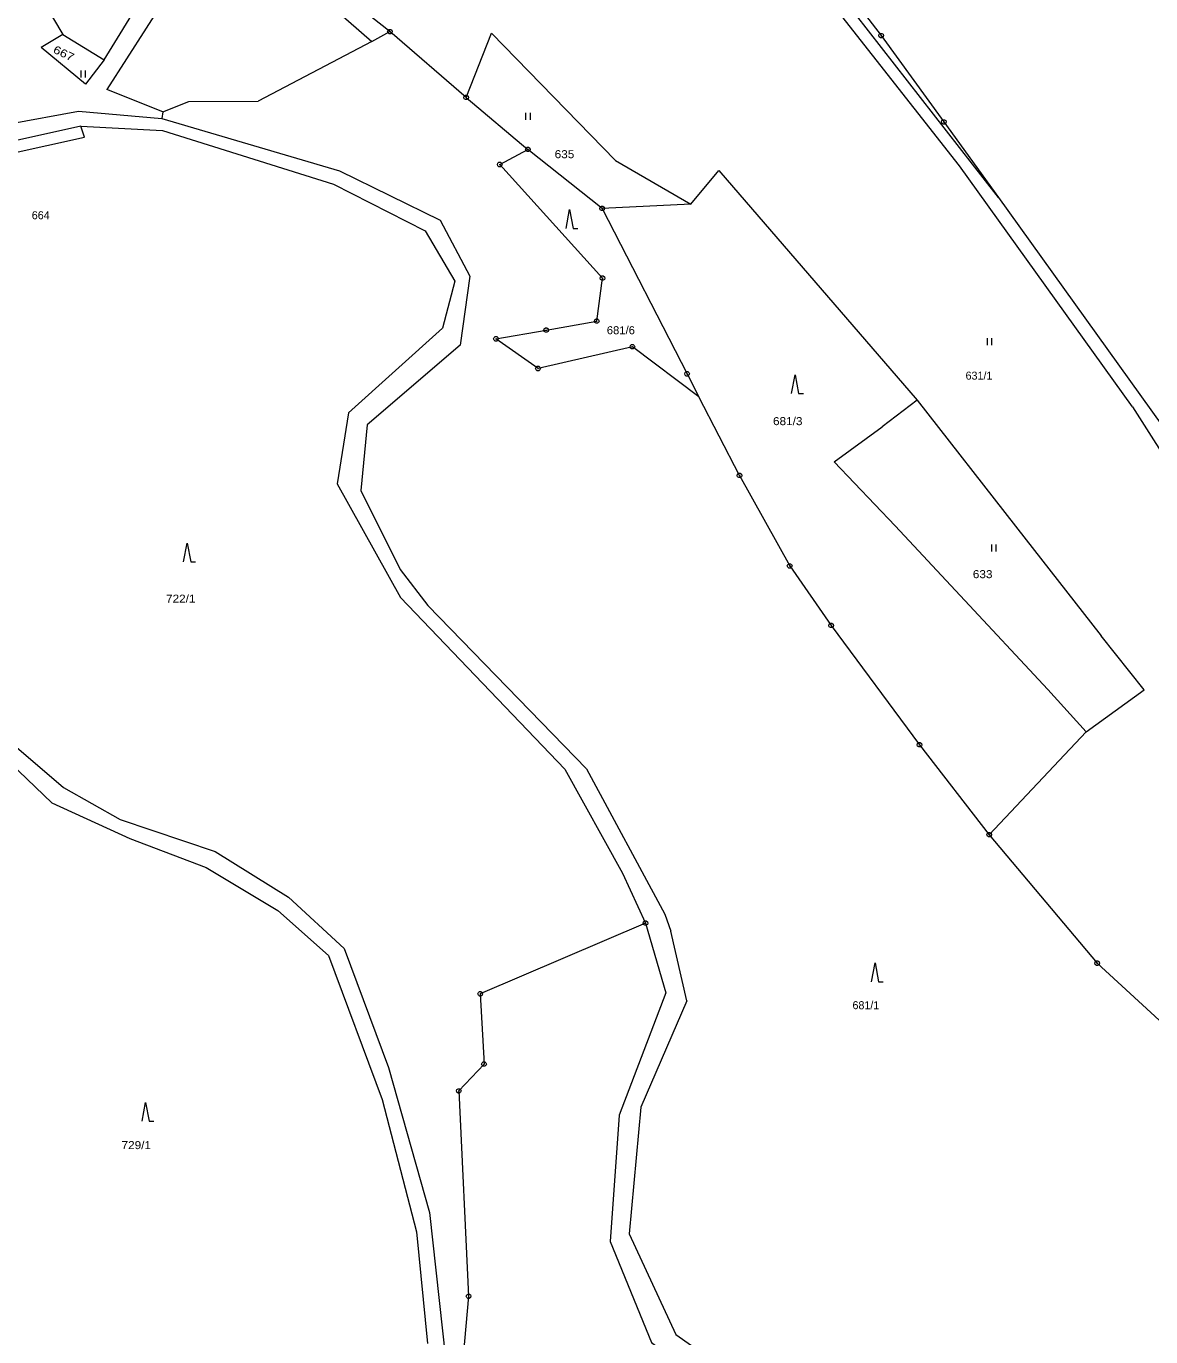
# Model space of a CAD drawing. Extents: x -687390 to -684106, y -954833 to -951648.
# Drawn here: x -686980 to -686741.2, y -953560.6 to -953282.2 of the extents above; entities that cross this region are included whole.
import ezdxf

# ---------------------------------------------------------------- set-up
doc = ezdxf.new("R2010")
doc.units = 0
doc.header["$LTSCALE"] = 0.68
for name, color, linetype, lineweight in [('1', 7, 'Continuous', 13), ('3', 7, 'Continuous', 13), ('7', 7, 'Continuous', 13), ('8', 7, 'Continuous', 13)]:
    doc.layers.add(name, color=color, linetype=linetype, lineweight=lineweight)
doc.layers.add('2', color=7, linetype='Continuous')

msp = doc.modelspace()

# ---------------------------------------------------------------- linework, layer by layer
at = {"layer": '1'}
for p, q in [((-686781.85, -953311.83), (-686824.32, -953257.77)), ((-686773.57, -953318.57), (-686815.59, -953264.66)), ((-686963.5, -953289.34), (-686953.7, -953273.35)), ((-686948.59, -953273.28), (-686962.93, -953295.64)), ((-686972.24, -953283.98), (-686976.87, -953286.71)), ((-686972.24, -953283.98), (-686963.5, -953289.34)), ((-686967.46, -953294.53), (-686976.87, -953286.71)), ((-686906.67, -953285.44), (-686930.78, -953298.14)), ((-686963.5, -953289.34), (-686967.46, -953294.53)), ((-686951.01, -953300.38), (-686962.93, -953295.64)), ((-686886.6, -953297.34), (-686873.5, -953308.38)), ((-686951.01, -953300.38), (-686951.22, -953301.78)), ((-686951.01, -953300.38), (-686945.51, -953298.23)), ((-686945.51, -953298.23), (-686930.78, -953298.14)), ((-686857.75, -953320.92), (-686873.5, -953308.38)), ((-686745.14, -953363.04), (-686781.85, -953311.83)), ((-686773.57, -953318.57), (-686738.91, -953366.96)), ((-686857.75, -953320.92), (-686839.71, -953356.04)), ((-686839.71, -953356.04), (-686837.19, -953360.91)), ((-686828.56, -953377.63), (-686837.19, -953360.91)), ((-686790.85, -953361.66), (-686798.26, -953367.32)), ((-686790.85, -953361.66), (-686769.96, -953388.38)), ((-686745.14, -953363.04), (-686717.92, -953405.86)), ((-686808.48, -953374.74), (-686798.26, -953367.32)), ((-686808.48, -953374.74), (-686795.5, -953388.35)), ((-686909.02, -953380.79), (-686900.61, -953397.57)), ((-686781.73, -953403.12), (-686795.5, -953388.35)), ((-686769.96, -953388.38), (-686751.78, -953411.72)), ((-686781.73, -953403.12), (-686763.1, -953423.09)), ((-686742.68, -953423.13), (-686751.78, -953411.72)), ((-686755, -953432.08), (-686763.1, -953423.09)), ((-686755, -953432.08), (-686742.68, -953423.13)), ((-686755, -953432.08), (-686775.54, -953453.93)), ((-686839.79, -953489.19), (-686843.13, -953474.4))]:
    msp.add_line(p, q, dxfattribs=at)
for points in [[(-686886.6, -953297.34), (-686902.8, -953283.36), (-686935.6, -953257.64), (-686954.5, -953239.63), (-686963.86, -953230.22)], [(-686954.5, -953239.63), (-686955.14, -953243.1), (-686906.67, -953285.44), (-686902.8, -953283.36)], [(-686834.02, -953240.95), (-686828.66, -953246.47), (-686819.24, -953257.21), (-686798.48, -953284.2), (-686785.18, -953302.55), (-686773.57, -953318.57)], [(-686980.31, -953270.4), (-686978.45, -953273.53), (-686972.24, -953283.98)], [(-686886.6, -953297.34), (-686881.25, -953283.7), (-686854.89, -953310.76), (-686838.93, -953320.02), (-686857.75, -953320.92)], [(-686983.56, -953302.91), (-686968.91, -953300.26), (-686951.22, -953301.78)], [(-686983.67, -953309.34), (-686967.63, -953305.8), (-686968.42, -953303.43), (-686982.1, -953306.46)], [(-686968.42, -953303.43), (-686951.12, -953304.38), (-686914.78, -953315.79), (-686895.36, -953325.65), (-686889, -953336.33), (-686891.63, -953346.36), (-686911.61, -953364.32), (-686914.03, -953379.41)], [(-686951.22, -953301.78), (-686913.54, -953312.92), (-686892.17, -953323.42), (-686885.83, -953335.3), (-686887.91, -953349.92), (-686907.67, -953366.85), (-686909.02, -953380.79)], [(-686837.19, -953360.91), (-686851.32, -953350.3), (-686871.36, -953354.92), (-686880.29, -953348.62), (-686869.64, -953346.75), (-686858.89, -953344.85), (-686857.66, -953335.71), (-686879.49, -953311.58), (-686873.5, -953308.38)], [(-686838.93, -953320.02), (-686832.95, -953312.88), (-686790.85, -953361.66)], [(-687037.88, -953375.05), (-687023.89, -953388.57), (-687013.39, -953396.86), (-686991.55, -953427.26), (-686972.13, -953443.92), (-686960.08, -953450.71), (-686939.95, -953457.51), (-686924.36, -953467.19), (-686912.54, -953478.09), (-686903.13, -953503.34), (-686894.42, -953534.14), (-686888.97, -953583.77)], [(-686828.56, -953377.63), (-686817.92, -953396.84), (-686809.1, -953409.49), (-686790.36, -953434.83), (-686775.54, -953453.93), (-686752.63, -953481.22), (-686722.86, -953508.62), (-686702.65, -953527.9), (-686683.54, -953543.96), (-686654.17, -953515.56), (-686625.49, -953536.15), (-686620.33, -953558.68), (-686617.35, -953559.12)], [(-686914.03, -953379.41), (-686900.53, -953403.56), (-686865.64, -953440.03), (-686853.41, -953462.06), (-686848.55, -953472.7), (-686844.24, -953487.5)], [(-687030.33, -953387.15), (-687019.11, -953395.83), (-686995.77, -953426.94), (-686974.61, -953447.17), (-686958.03, -953454.71), (-686941.83, -953460.86), (-686926.64, -953470), (-686915.85, -953479.55), (-686904.42, -953510.15), (-686897.13, -953538.3), (-686894.86, -953562.01)], [(-686900.61, -953397.57), (-686894.74, -953405.22), (-686861.09, -953439.96), (-686844.41, -953470.8), (-686843.13, -953474.4)], [(-686848.55, -953472.7), (-686883.62, -953487.73), (-686882.83, -953502.66), (-686888.19, -953508.36), (-686886.1, -953551.96), (-686888.97, -953583.77)], [(-686844.24, -953487.5), (-686854.12, -953513.48), (-686856.02, -953540.32), (-686847.26, -953561.75), (-686819.56, -953582.52), (-686787.55, -953594.55), (-686737.1, -953603.57), (-686706.26, -953623.07), (-686659.76, -953633.42), (-686631.23, -953646.66)], [(-686839.79, -953489.19), (-686849.5, -953511.8), (-686851.99, -953538.73), (-686842.1, -953560.06), (-686816.44, -953578.15), (-686785.17, -953591.65), (-686735.45, -953601.12), (-686703.86, -953620.79), (-686657.58, -953631.09), (-686629.18, -953645.02), (-686610.63, -953664.49), (-686593.4, -953691.27), (-686585.18, -953724.8), (-686575.37, -953740.35), (-686548.41, -953769.8), (-686529.04, -953794.51)]]:
    msp.add_lwpolyline(points, dxfattribs=at)
at = {"layer": '3'}
for p, q in [((-686968.46, -953291.62), (-686968.46, -953293.12)), ((-686967.46, -953293.12), (-686967.46, -953291.62)), ((-686873.99, -953300.6), (-686873.99, -953302.1)), ((-686872.99, -953302.1), (-686872.99, -953300.6)), ((-686775.97, -953348.46), (-686775.97, -953349.96)), ((-686774.97, -953349.96), (-686774.97, -953348.46)), ((-686775.06, -953392.31), (-686775.06, -953393.81)), ((-686774.06, -953393.81), (-686774.06, -953392.31))]:
    msp.add_line(p, q, dxfattribs=at)
for points in [[(-686865.4, -953325.17), (-686864.65, -953321.17), (-686863.9, -953325.17), (-686862.9, -953325.17)], [(-686817.52, -953360.23), (-686816.77, -953356.23), (-686816.02, -953360.23), (-686815.02, -953360.23)], [(-686946.61, -953395.99), (-686945.86, -953391.99), (-686945.11, -953395.99), (-686944.11, -953395.99)], [(-686800.55, -953485.16), (-686799.8, -953481.16), (-686799.05, -953485.16), (-686798.05, -953485.16)], [(-686955.44, -953514.79), (-686954.69, -953510.79), (-686953.94, -953514.79), (-686952.94, -953514.79)]]:
    msp.add_lwpolyline(points, dxfattribs=at)
at = {"layer": '8'}
for p, q in [((-686902.92, -953283.36), (-686902.68, -953283.36)), ((-686798.6, -953284.2), (-686798.36, -953284.2)), ((-686886.72, -953297.34), (-686886.48, -953297.34)), ((-686785.3, -953302.55), (-686785.06, -953302.55)), ((-686873.62, -953308.38), (-686873.38, -953308.38)), ((-686879.61, -953311.58), (-686879.37, -953311.58)), ((-686857.87, -953320.92), (-686857.63, -953320.92)), ((-686857.78, -953335.71), (-686857.54, -953335.71)), ((-686859.01, -953344.85), (-686858.77, -953344.85)), ((-686869.76, -953346.75), (-686869.52, -953346.75)), ((-686880.41, -953348.62), (-686880.17, -953348.62)), ((-686851.44, -953350.3), (-686851.2, -953350.3)), ((-686871.48, -953354.92), (-686871.24, -953354.92)), ((-686839.83, -953356.04), (-686839.59, -953356.04)), ((-686828.68, -953377.63), (-686828.44, -953377.63)), ((-686818.04, -953396.84), (-686817.8, -953396.84)), ((-686809.22, -953409.49), (-686808.98, -953409.49)), ((-686790.48, -953434.83), (-686790.24, -953434.83)), ((-686775.66, -953453.93), (-686775.42, -953453.93)), ((-686848.67, -953472.7), (-686848.43, -953472.7)), ((-686752.75, -953481.22), (-686752.51, -953481.22)), ((-686883.74, -953487.73), (-686883.5, -953487.73)), ((-686882.95, -953502.66), (-686882.71, -953502.66)), ((-686888.31, -953508.36), (-686888.07, -953508.36)), ((-686886.22, -953551.96), (-686885.98, -953551.96))]:
    msp.add_line(p, q, dxfattribs=at)
for points in [[(-686902.65, -953282.88), (-686902.4, -953283.06), (-686902.3, -953283.35), (-686902.4, -953283.64), (-686902.65, -953283.82), (-686902.96, -953283.82), (-686903.21, -953283.64), (-686903.31, -953283.35), (-686903.21, -953283.06), (-686902.96, -953282.88)], [(-686798.33, -953283.72), (-686798.08, -953283.9), (-686797.98, -953284.19), (-686798.08, -953284.48), (-686798.33, -953284.66), (-686798.64, -953284.66), (-686798.89, -953284.48), (-686798.99, -953284.19), (-686798.89, -953283.9), (-686798.64, -953283.72)], [(-686886.45, -953296.86), (-686886.2, -953297.04), (-686886.1, -953297.33), (-686886.2, -953297.62), (-686886.45, -953297.8), (-686886.76, -953297.8), (-686887.01, -953297.62), (-686887.11, -953297.33), (-686887.01, -953297.04), (-686886.76, -953296.86)], [(-686785.03, -953302.07), (-686784.78, -953302.25), (-686784.68, -953302.54), (-686784.78, -953302.83), (-686785.03, -953303.01), (-686785.34, -953303.01), (-686785.59, -953302.83), (-686785.69, -953302.54), (-686785.59, -953302.25), (-686785.34, -953302.07)], [(-686873.35, -953307.9), (-686873.1, -953308.08), (-686873, -953308.37), (-686873.1, -953308.66), (-686873.35, -953308.84), (-686873.66, -953308.84), (-686873.91, -953308.66), (-686874.01, -953308.37), (-686873.91, -953308.08), (-686873.66, -953307.9)], [(-686879.34, -953311.1), (-686879.09, -953311.28), (-686878.99, -953311.57), (-686879.09, -953311.86), (-686879.34, -953312.04), (-686879.65, -953312.04), (-686879.9, -953311.86), (-686880, -953311.57), (-686879.9, -953311.28), (-686879.65, -953311.1)], [(-686857.6, -953320.44), (-686857.35, -953320.62), (-686857.25, -953320.91), (-686857.35, -953321.2), (-686857.6, -953321.38), (-686857.91, -953321.38), (-686858.16, -953321.2), (-686858.26, -953320.91), (-686858.16, -953320.62), (-686857.91, -953320.44)], [(-686857.51, -953335.23), (-686857.26, -953335.41), (-686857.16, -953335.7), (-686857.26, -953335.99), (-686857.51, -953336.17), (-686857.82, -953336.17), (-686858.07, -953335.99), (-686858.17, -953335.7), (-686858.07, -953335.41), (-686857.82, -953335.23)], [(-686858.74, -953344.37), (-686858.49, -953344.55), (-686858.39, -953344.84), (-686858.49, -953345.13), (-686858.74, -953345.31), (-686859.05, -953345.31), (-686859.3, -953345.13), (-686859.4, -953344.84), (-686859.3, -953344.55), (-686859.05, -953344.37)], [(-686869.49, -953346.27), (-686869.24, -953346.45), (-686869.14, -953346.74), (-686869.24, -953347.03), (-686869.49, -953347.21), (-686869.8, -953347.21), (-686870.05, -953347.03), (-686870.15, -953346.74), (-686870.05, -953346.45), (-686869.8, -953346.27)], [(-686880.14, -953348.14), (-686879.89, -953348.32), (-686879.79, -953348.61), (-686879.89, -953348.9), (-686880.14, -953349.08), (-686880.45, -953349.08), (-686880.7, -953348.9), (-686880.8, -953348.61), (-686880.7, -953348.32), (-686880.45, -953348.14)], [(-686851.17, -953349.82), (-686850.92, -953350), (-686850.82, -953350.29), (-686850.92, -953350.58), (-686851.17, -953350.76), (-686851.48, -953350.76), (-686851.73, -953350.58), (-686851.83, -953350.29), (-686851.73, -953350), (-686851.48, -953349.82)], [(-686871.21, -953354.44), (-686870.96, -953354.62), (-686870.86, -953354.91), (-686870.96, -953355.2), (-686871.21, -953355.38), (-686871.52, -953355.38), (-686871.77, -953355.2), (-686871.87, -953354.91), (-686871.77, -953354.62), (-686871.52, -953354.44)], [(-686839.56, -953355.56), (-686839.31, -953355.74), (-686839.21, -953356.03), (-686839.31, -953356.32), (-686839.56, -953356.5), (-686839.87, -953356.5), (-686840.12, -953356.32), (-686840.22, -953356.03), (-686840.12, -953355.74), (-686839.87, -953355.56)], [(-686828.41, -953377.15), (-686828.16, -953377.33), (-686828.06, -953377.62), (-686828.16, -953377.91), (-686828.41, -953378.09), (-686828.72, -953378.09), (-686828.97, -953377.91), (-686829.07, -953377.62), (-686828.97, -953377.33), (-686828.72, -953377.15)], [(-686817.77, -953396.36), (-686817.52, -953396.54), (-686817.42, -953396.83), (-686817.52, -953397.12), (-686817.77, -953397.3), (-686818.08, -953397.3), (-686818.33, -953397.12), (-686818.43, -953396.83), (-686818.33, -953396.54), (-686818.08, -953396.36)], [(-686808.95, -953409.01), (-686808.7, -953409.19), (-686808.6, -953409.48), (-686808.7, -953409.77), (-686808.95, -953409.95), (-686809.26, -953409.95), (-686809.51, -953409.77), (-686809.61, -953409.48), (-686809.51, -953409.19), (-686809.26, -953409.01)], [(-686790.21, -953434.35), (-686789.96, -953434.53), (-686789.86, -953434.82), (-686789.96, -953435.11), (-686790.21, -953435.29), (-686790.52, -953435.29), (-686790.77, -953435.11), (-686790.87, -953434.82), (-686790.77, -953434.53), (-686790.52, -953434.35)], [(-686775.39, -953453.45), (-686775.14, -953453.63), (-686775.04, -953453.92), (-686775.14, -953454.21), (-686775.39, -953454.39), (-686775.7, -953454.39), (-686775.95, -953454.21), (-686776.05, -953453.92), (-686775.95, -953453.63), (-686775.7, -953453.45)], [(-686848.4, -953472.22), (-686848.15, -953472.4), (-686848.05, -953472.69), (-686848.15, -953472.98), (-686848.4, -953473.16), (-686848.71, -953473.16), (-686848.96, -953472.98), (-686849.06, -953472.69), (-686848.96, -953472.4), (-686848.71, -953472.22)], [(-686752.48, -953480.74), (-686752.23, -953480.92), (-686752.13, -953481.21), (-686752.23, -953481.5), (-686752.48, -953481.68), (-686752.79, -953481.68), (-686753.04, -953481.5), (-686753.14, -953481.21), (-686753.04, -953480.92), (-686752.79, -953480.74)], [(-686883.47, -953487.25), (-686883.22, -953487.43), (-686883.12, -953487.72), (-686883.22, -953488.01), (-686883.47, -953488.19), (-686883.78, -953488.19), (-686884.03, -953488.01), (-686884.13, -953487.72), (-686884.03, -953487.43), (-686883.78, -953487.25)], [(-686882.68, -953502.18), (-686882.43, -953502.36), (-686882.33, -953502.65), (-686882.43, -953502.94), (-686882.68, -953503.12), (-686882.99, -953503.12), (-686883.24, -953502.94), (-686883.34, -953502.65), (-686883.24, -953502.36), (-686882.99, -953502.18)], [(-686888.04, -953507.88), (-686887.79, -953508.06), (-686887.69, -953508.35), (-686887.79, -953508.64), (-686888.04, -953508.82), (-686888.35, -953508.82), (-686888.6, -953508.64), (-686888.7, -953508.35), (-686888.6, -953508.06), (-686888.35, -953507.88)], [(-686885.95, -953551.48), (-686885.7, -953551.66), (-686885.6, -953551.95), (-686885.7, -953552.24), (-686885.95, -953552.42), (-686886.26, -953552.42), (-686886.51, -953552.24), (-686886.61, -953551.95), (-686886.51, -953551.66), (-686886.26, -953551.48)]]:
    msp.add_lwpolyline(points, close=True, dxfattribs=at)

# ---------------------------------------------------------------- texts
at = {"layer": '2', "width": 1.2}
msp.add_text('667', height=1.7, rotation=334.837, dxfattribs=at).set_placement((-686974.484, -953287.774))
at = {"layer": '2'}
for s, width, p in [('635', 1.1, (-686867.826, -953310.24)), ('681/6', 1.05, (-686856.756, -953347.63)), ('681/3', 1.1, (-686821.466, -953366.94)), ('633', 1.1, (-686779.036, -953399.44)), ('722/1', 1.1, (-686950.355, -953404.64)), ('729/1', 1.1, (-686959.795, -953520.7))]:
    msp.add_text(s, height=1.7, dxfattribs=dict(at, width=width)).set_placement(p)
for s, p in [('631/1', (-686780.576, -953357.27)), ('681/1', (-686804.586, -953490.99))]:
    msp.add_text(s, height=1.7, dxfattribs=at).set_placement(p)
at = {"layer": '7'}
msp.add_text('664', height=1.7, dxfattribs=at).set_placement((-686978.856, -953323.21))

doc.saveas('drawing.dxf')
